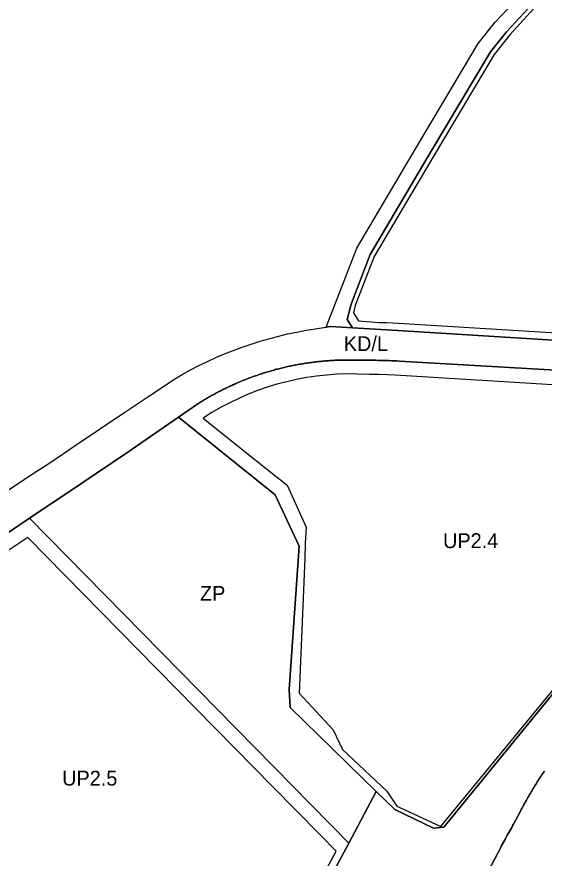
# Model space of a CAD drawing. Extents: x -297746 to -295403, y 27112 to 28877.
# Drawn here: x -296657 to -296302, y 27910 to 28476 of the extents above; entities that cross this region are included whole.
import ezdxf

# ---------------------------------------------------------------- set-up
doc = ezdxf.new("R2010")
doc.units = 0
for name, color, linetype in [('linie_rozgraniczajace', 7, 'Continuous'), ('linie_zabudowy_nieprzekraczalne', 7, 'Continuous'), ('linie_zabudowy_obowiazujace', 7, 'Continuous'), ('oznaczenia_przeznaczen', 7, 'Continuous')]:
    doc.layers.add(name, color=color, linetype=linetype)

msp = doc.modelspace()

# ---------------------------------------------------------------- linework, layer by layer
at = {"layer": 'linie_rozgraniczajace'}
for points in [[(-296431.166, 28266.781), (-296445.936, 28267.695), (-296448.743, 28267.269), (-296428.141, 28320.388), (-296387.321, 28389.589), (-296346.506, 28458.251), (-296335.072, 28472.554), (-296317.92, 28490.672)], [(-296306.95, 28488.333), (-296327.479, 28466.037), (-296338.263, 28452.547), (-296378.717, 28384.494), (-296419.113, 28316.011), (-296432.067, 28282.612), (-296434.768, 28272.351), (-296431.166, 28266.781)], [(-296288.797, 28257.976), (-296400.521, 28264.886), (-296431.166, 28266.781), (-296434.768, 28272.351), (-296432.067, 28282.612), (-296419.113, 28316.011), (-296378.717, 28384.494), (-296338.263, 28452.547), (-296327.479, 28466.037), (-296306.95, 28488.333)], [(-296733.569, 28109.944), (-296648.599, 28167.051), (-296634.84, 28175.815), (-296617.12, 28187.98), (-296584.42, 28209.83), (-296576.285, 28215.265), (-296568.15, 28220.7), (-296562.44, 28224.51), (-296555.985, 28228.825), (-296549.53, 28233.14), (-296545.77, 28235.3), (-296540.18, 28238.35), (-296534.54, 28241.26), (-296529.26, 28243.84), (-296523.04, 28246.68), (-296517.2, 28249.18), (-296505.34, 28253.75), (-296499.33, 28255.83), (-296493.27, 28257.75), (-296484.97, 28260.1), (-296474.84, 28262.64), (-296468.61, 28263.9), (-296462.38, 28265.16), (-296459.245, 28265.675), (-296448.743, 28267.269), (-296445.936, 28267.695), (-296431.166, 28266.781), (-296400.521, 28264.886), (-296288.797, 28257.976)], [(-296376.508, 27929.794), (-296402.601, 27942.294), (-296415.218, 27954.583), (-296473.152, 28011.013), (-296473.784, 28023.153), (-296466.991, 28119.736), (-296483.19, 28154.381), (-296548.335, 28206.521), (-296535.256, 28215.538), (-296534.559, 28215.98), (-296533.824, 28216.441), (-296533.086, 28216.899), (-296532.347, 28217.354), (-296531.605, 28217.806), (-296530.861, 28218.254), (-296530.115, 28218.698), (-296529.367, 28219.139), (-296528.617, 28219.577), (-296527.865, 28220.011), (-296527.111, 28220.442), (-296526.355, 28220.869), (-296525.597, 28221.293), (-296524.838, 28221.713), (-296524.076, 28222.13), (-296523.312, 28222.543), (-296522.547, 28222.953), (-296521.779, 28223.359), (-296521.01, 28223.762), (-296520.239, 28224.161), (-296519.466, 28224.557), (-296518.691, 28224.949), (-296517.914, 28225.337), (-296517.136, 28225.722), (-296516.356, 28226.103), (-296515.574, 28226.481), (-296514.79, 28226.855), (-296514.005, 28227.225), (-296513.218, 28227.592), (-296512.429, 28227.955), (-296511.639, 28228.315), (-296510.847, 28228.671), (-296510.053, 28229.023), (-296509.258, 28229.372), (-296508.461, 28229.717), (-296507.662, 28230.058), (-296506.862, 28230.395), (-296506.061, 28230.729), (-296505.258, 28231.059), (-296504.453, 28231.386), (-296503.647, 28231.709), (-296502.839, 28232.028), (-296502.03, 28232.343), (-296501.22, 28232.655), (-296500.408, 28232.963), (-296499.594, 28233.267), (-296498.78, 28233.567), (-296497.964, 28233.864), (-296497.146, 28234.156), (-296496.327, 28234.446), (-296495.507, 28234.731), (-296494.686, 28235.012), (-296493.863, 28235.29), (-296493.039, 28235.564), (-296492.214, 28235.834), (-296491.387, 28236.101), (-296490.56, 28236.363), (-296489.731, 28236.622), (-296488.901, 28236.877), (-296488.069, 28237.128), (-296487.237, 28237.375), (-296486.404, 28237.618), (-296485.569, 28237.858), (-296484.733, 28238.094), (-296483.896, 28238.326), (-296483.059, 28238.554), (-296482.22, 28238.778), (-296481.38, 28238.998), (-296480.539, 28239.214), (-296479.697, 28239.427), (-296478.854, 28239.636), (-296478.01, 28239.84), (-296477.165, 28240.041), (-296476.32, 28240.238), (-296475.473, 28240.431), (-296474.626, 28240.62), (-296473.777, 28240.806), (-296472.928, 28240.987), (-296472.078, 28241.165), (-296471.227, 28241.338), (-296470.376, 28241.508), (-296469.523, 28241.673), (-296468.67, 28241.835), (-296467.816, 28241.993), (-296466.962, 28242.147), (-296466.106, 28242.297), (-296465.25, 28242.443), (-296464.394, 28242.585), (-296463.536, 28242.723), (-296462.679, 28242.857), (-296461.82, 28242.987)], [(-296408.43, 28244.669), (-296410.207, 28244.722), (-296411.984, 28244.77), (-296413.761, 28244.814), (-296415.538, 28244.855), (-296417.316, 28244.891), (-296419.094, 28244.924), (-296420.871, 28244.952), (-296422.649, 28244.976), (-296424.427, 28244.997), (-296426.204, 28245.013), (-296427.982, 28245.026), (-296429.76, 28245.034), (-296431.531, 28245.038), (-296432.399, 28245.048), (-296433.267, 28245.053), (-296434.136, 28245.054), (-296435.004, 28245.052), (-296435.872, 28245.045), (-296436.741, 28245.034), (-296437.609, 28245.019), (-296438.477, 28245.001), (-296439.345, 28244.978), (-296440.213, 28244.951), (-296441.081, 28244.921), (-296441.948, 28244.886), (-296442.816, 28244.847), (-296443.683, 28244.804), (-296444.55, 28244.758), (-296445.417, 28244.707), (-296446.284, 28244.652), (-296447.15, 28244.594), (-296448.016, 28244.531), (-296448.882, 28244.465), (-296449.747, 28244.394), (-296450.612, 28244.319), (-296451.477, 28244.241), (-296452.341, 28244.158), (-296453.205, 28244.072), (-296454.069, 28243.981), (-296454.932, 28243.886), (-296455.795, 28243.788), (-296456.657, 28243.685), (-296457.519, 28243.579), (-296458.38, 28243.469), (-296459.241, 28243.354), (-296460.101, 28243.236), (-296460.961, 28243.114), (-296461.82, 28242.987), (-296462.679, 28242.857), (-296463.536, 28242.723), (-296464.394, 28242.585), (-296465.25, 28242.443), (-296466.106, 28242.297), (-296466.962, 28242.147), (-296467.816, 28241.993), (-296468.67, 28241.835), (-296469.523, 28241.673), (-296470.376, 28241.508), (-296471.227, 28241.338), (-296472.078, 28241.165), (-296472.928, 28240.987), (-296473.777, 28240.806), (-296474.626, 28240.62), (-296475.473, 28240.431), (-296476.32, 28240.238), (-296477.165, 28240.041), (-296478.01, 28239.84), (-296478.854, 28239.636), (-296479.697, 28239.427), (-296480.539, 28239.214), (-296481.38, 28238.998), (-296482.22, 28238.778), (-296483.059, 28238.554), (-296483.896, 28238.326), (-296484.733, 28238.094), (-296485.569, 28237.858), (-296486.404, 28237.618), (-296487.237, 28237.375), (-296488.069, 28237.128), (-296488.901, 28236.877), (-296489.731, 28236.622), (-296490.56, 28236.363), (-296491.387, 28236.101), (-296492.214, 28235.834), (-296493.039, 28235.564), (-296493.863, 28235.29), (-296494.686, 28235.012), (-296495.507, 28234.731), (-296496.327, 28234.446), (-296497.146, 28234.156), (-296497.964, 28233.864), (-296498.78, 28233.567), (-296499.594, 28233.267), (-296500.408, 28232.963), (-296501.22, 28232.655), (-296502.03, 28232.343), (-296502.839, 28232.028), (-296503.647, 28231.709), (-296504.453, 28231.386)], [(-296461.82, 28242.987), (-296460.961, 28243.114), (-296460.101, 28243.236), (-296459.241, 28243.354), (-296458.38, 28243.469), (-296457.519, 28243.579), (-296456.657, 28243.685), (-296455.795, 28243.788), (-296454.932, 28243.886), (-296454.069, 28243.981), (-296453.205, 28244.072), (-296452.341, 28244.158), (-296451.477, 28244.241), (-296450.612, 28244.319), (-296449.747, 28244.394), (-296448.882, 28244.465), (-296448.016, 28244.531), (-296447.15, 28244.594), (-296446.284, 28244.652), (-296445.417, 28244.707), (-296444.55, 28244.758), (-296443.683, 28244.804), (-296442.816, 28244.847), (-296441.948, 28244.886), (-296441.081, 28244.921), (-296440.213, 28244.951), (-296439.345, 28244.978), (-296438.477, 28245.001), (-296437.609, 28245.019), (-296436.741, 28245.034), (-296435.872, 28245.045), (-296435.004, 28245.052), (-296434.136, 28245.054), (-296433.267, 28245.053), (-296432.399, 28245.048), (-296431.531, 28245.038), (-296429.76, 28245.034), (-296427.982, 28245.026), (-296426.204, 28245.013), (-296424.427, 28244.997), (-296422.649, 28244.976), (-296420.871, 28244.952), (-296419.094, 28244.924), (-296417.316, 28244.891), (-296415.538, 28244.855), (-296413.761, 28244.814), (-296411.984, 28244.77), (-296410.207, 28244.722), (-296408.43, 28244.669), (-296406.653, 28244.613), (-296404.876, 28244.552), (-296403.099, 28244.488), (-296401.323, 28244.42), (-296399.546, 28244.347), (-296259.148, 28236.105)], [(-296259.148, 28236.105), (-296399.546, 28244.347), (-296401.323, 28244.42), (-296403.099, 28244.488), (-296404.876, 28244.552), (-296406.653, 28244.613), (-296408.43, 28244.669)], [(-296504.453, 28231.386), (-296505.258, 28231.059), (-296506.061, 28230.729), (-296506.862, 28230.395), (-296507.662, 28230.058), (-296508.461, 28229.717), (-296509.258, 28229.372), (-296510.053, 28229.023), (-296510.847, 28228.671), (-296511.639, 28228.315), (-296512.429, 28227.955), (-296513.218, 28227.592), (-296514.005, 28227.225), (-296514.79, 28226.855), (-296515.574, 28226.481), (-296516.356, 28226.103), (-296517.136, 28225.722), (-296517.914, 28225.337), (-296518.691, 28224.949), (-296519.466, 28224.557), (-296520.239, 28224.161), (-296521.01, 28223.762), (-296521.779, 28223.359), (-296522.547, 28222.953), (-296523.312, 28222.543), (-296524.076, 28222.13), (-296524.838, 28221.713), (-296525.597, 28221.293), (-296526.355, 28220.869), (-296527.111, 28220.442), (-296527.865, 28220.011), (-296528.617, 28219.577), (-296529.367, 28219.139), (-296530.115, 28218.698), (-296530.861, 28218.254), (-296531.605, 28217.806), (-296532.347, 28217.354), (-296533.086, 28216.899), (-296533.824, 28216.441), (-296534.559, 28215.98), (-296535.256, 28215.538), (-296548.335, 28206.521), (-296582.332, 28183.081), (-296613.955, 28161.767), (-296648.438, 28138.524), (-296676.764, 28119.432)], [(-296451.602, 27886.266), (-296433.475, 27919.768), (-296415.218, 27954.583), (-296402.601, 27942.294), (-296376.508, 27929.794), (-296369.501, 27930.579), (-296150.685, 28198.209)], [(-296150.685, 28198.209), (-296369.501, 27930.579), (-296376.508, 27929.794)], [(-296676.764, 28119.432), (-296648.438, 28138.524), (-296433.475, 27919.768), (-296451.602, 27886.266), (-296706.72, 27821.429)], [(-296374.255, 27835.235), (-296331.038, 27917.337), (-296330.897, 27917.605), (-296330.28, 27918.77), (-296329.66, 27919.934), (-296329.037, 27921.095), (-296328.409, 27922.255), (-296327.779, 27923.412), (-296327.144, 27924.568), (-296326.507, 27925.722), (-296325.865, 27926.874), (-296325.221, 27928.024), (-296324.572, 27929.171), (-296323.921, 27930.317), (-296323.266, 27931.461), (-296322.607, 27932.603), (-296318.273, 27940.837), (-296317.757, 27941.812), (-296317.238, 27942.785), (-296316.716, 27943.756), (-296316.19, 27944.726), (-296315.66, 27945.693), (-296315.127, 27946.659), (-296314.591, 27947.622), (-296314.05, 27948.584), (-296313.507, 27949.544), (-296312.96, 27950.501), (-296312.409, 27951.457), (-296311.855, 27952.411), (-296311.298, 27953.362), (-296310.737, 27954.312), (-296310.173, 27955.26), (-296309.605, 27956.205), (-296309.034, 27957.149), (-296308.459, 27958.09), (-296307.881, 27959.029), (-296307.3, 27959.967), (-296306.715, 27960.902), (-296306.127, 27961.835), (-296305.535, 27962.765), (-296304.94, 27963.694), (-296304.342, 27964.621), (-296303.74, 27965.545), (-296303.135, 27966.467), (-296302.527, 27967.387), (-296301.915, 27968.305)], [(-296301.915, 27968.305), (-296302.527, 27967.387), (-296303.135, 27966.467), (-296303.74, 27965.545), (-296304.342, 27964.621), (-296304.94, 27963.694), (-296305.535, 27962.765), (-296306.127, 27961.835), (-296306.715, 27960.902), (-296307.3, 27959.967), (-296307.881, 27959.029), (-296308.459, 27958.09), (-296309.034, 27957.149), (-296309.605, 27956.205), (-296310.173, 27955.26), (-296310.737, 27954.312), (-296311.298, 27953.362), (-296311.855, 27952.411), (-296312.409, 27951.457), (-296312.96, 27950.501), (-296313.507, 27949.544), (-296314.05, 27948.584), (-296314.591, 27947.622)], [(-296314.591, 27947.622), (-296315.127, 27946.659), (-296315.66, 27945.693), (-296316.19, 27944.726), (-296316.716, 27943.756), (-296317.238, 27942.785), (-296317.757, 27941.812), (-296318.273, 27940.837), (-296322.607, 27932.603), (-296323.266, 27931.461), (-296323.921, 27930.317), (-296324.572, 27929.171), (-296325.221, 27928.024), (-296325.865, 27926.874), (-296326.507, 27925.722), (-296327.144, 27924.568), (-296327.779, 27923.412), (-296328.409, 27922.255), (-296329.037, 27921.095), (-296329.66, 27919.934), (-296330.28, 27918.77), (-296330.897, 27917.605), (-296331.038, 27917.337), (-296374.255, 27835.235)]]:
    msp.add_lwpolyline(points, dxfattribs=at)
msp.add_lwpolyline([(-296433.475, 27919.768), (-296648.438, 28138.524), (-296613.955, 28161.767), (-296582.332, 28183.081), (-296548.335, 28206.521), (-296483.19, 28154.381), (-296466.991, 28119.736), (-296473.784, 28023.153), (-296473.152, 28011.013), (-296415.218, 27954.583)], close=True, dxfattribs=at)
at = {"layer": 'linie_zabudowy_nieprzekraczalne'}
for points in [[(-296413.159, 28270.416), (-296410.576, 28270.359), (-296408.157, 28270.284), (-296404.116, 28270.108), (-296400.188, 28269.877), (-296290.072, 28263.067), (-296278.889, 28269.983), (-296272.337, 28285.427), (-296270.012, 28290.744), (-296267.355, 28296.462), (-296263.995, 28303.222), (-296260.355, 28310.046), (-296256.535, 28316.733), (-296251.981, 28324.158), (-296247.403, 28331.111), (-296243.646, 28336.483), (-296239.133, 28342.583), (-296233.835, 28349.305), (-296163.69, 28435.416), (-296118.009, 28499.829)], [(-296304.656, 28486.394), (-296325.198, 28464.084), (-296335.788, 28450.838), (-296376.133, 28382.967), (-296416.402, 28314.699), (-296429.205, 28281.687), (-296430.485, 28276.824), (-296426.987, 28271.415), (-296413.159, 28270.416)], [(-296260.782, 28065.779), (-296180.491, 28175.971), (-296158.146, 28203.301), (-296165.678, 28208.227), (-296172.301, 28211.709), (-296183.46, 28216.036), (-296190.019, 28217.942), (-296228.116, 28223.114), (-296236.121, 28224.076), (-296242.75, 28224.77), (-296248.13, 28225.264), (-296253.508, 28225.698), (-296257.663, 28225.991), (-296259.763, 28226.126), (-296402.37, 28234.945), (-296407.477, 28235.034), (-296413.394, 28235.209), (-296419.612, 28235.364), (-296427.828, 28235.627)], [(-296531.64, 28205.972), (-296503.264, 28183.261), (-296475.116, 28160.732), (-296462.186, 28132.443), (-296462.93, 28121.581), (-296463.289, 28111.558), (-296466.986, 28020.721), (-296444.193, 27996.003), (-296437.926, 27982.786), (-296407.965, 27954.77), (-296401.132, 27944.681), (-296393.473, 27941.127), (-296371.595, 27930.975), (-296358.283, 27947.17)], [(-296649.741, 28125.587), (-296679.465, 28105.72), (-296681.763, 28104.411), (-296712.278, 28086.739), (-296715.138, 28081.914), (-296714.191, 28009.758), (-296712.447, 27877.015), (-296711.852, 27831.672), (-296705.598, 27826.874), (-296660.684, 27838.289), (-296525.454, 27872.657), (-296474.728, 27885.549), (-296454.954, 27890.574), (-296442.117, 27914.3), (-296453.116, 27925.493)], [(-296484.612, 27957.545), (-296575.408, 28049.943), (-296649.741, 28125.587)]]:
    msp.add_lwpolyline(points, dxfattribs=at)
msp.add_arc((-296432.13, 28054.154), 181.524, 88.64201, 123.243, dxfattribs=at)
at = {"layer": 'linie_zabudowy_obowiazujace'}
for points in [[(-296358.283, 27947.17), (-296260.782, 28065.779)], [(-296453.116, 27925.493), (-296484.612, 27957.545)], [(-296453.116, 27925.493), (-296484.612, 27957.545)]]:
    msp.add_lwpolyline(points, dxfattribs=at)

# ---------------------------------------------------------------- texts
at = {"layer": 'oznaczenia_przeznaczen'}
for s, p in [('KD/L', (-296436.945, 28251.084)), ('UP2.4', (-296370.122, 28118.387)), ('ZP', (-296533.824, 28082.928)), ('UP2.5', (-296626.564, 27958.469))]:
    msp.add_text(s, height=10, dxfattribs=at).set_placement(p)

doc.saveas('drawing.dxf')
